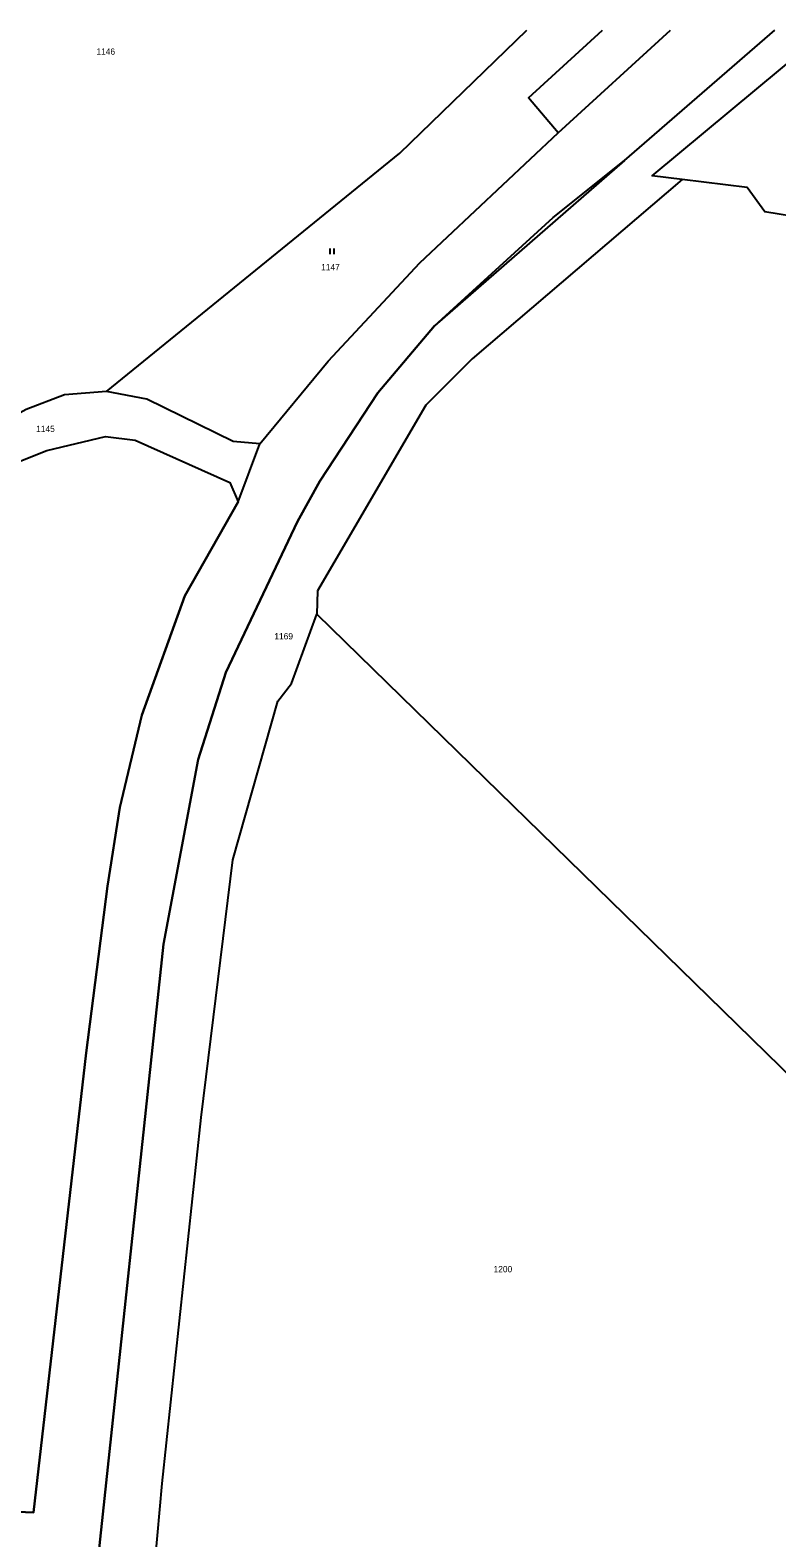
# Model space of a CAD drawing. Extents: x -520431 to -517205, y -1075927 to -1074013.
# Drawn here: x -517614 to -517411.8, y -1074423.3 to -1074014.8 of the extents above; entities that cross this region are included whole.
import ezdxf

# ---------------------------------------------------------------- set-up
doc = ezdxf.new("R2010")
doc.units = 0
for name, color, linetype in [('Hranice parcel', 7, 'Continuous'), ('Parcelní čísla', 7, 'Continuous'), ('Vrstva 54', 7, 'Continuous'), ('Značky kultur', 7, 'Continuous')]:
    doc.layers.add(name, color=color, linetype=linetype)

msp = doc.modelspace()

# ---------------------------------------------------------------- linework, layer by layer
at = {"layer": 'Hranice parcel'}
msp.add_line((-517557.7, -1074142.56), (-517551.84, -1074126.89), dxfattribs=at)
for points in [[(-517596.08, -1074449.57), (-517597.12, -1074446.25), (-517596.45, -1074436.33), (-517577.92, -1074262.43), (-517568.47, -1074212.35), (-517561.03, -1074188.8), (-517541.56, -1074147.89), (-517535.52, -1074136.96), (-517519.8, -1074113.04), (-517504.53, -1074094.89), (-517472.33, -1074065.57), (-517453.06, -1074050.06), (-517412.3, -1074014.78)], [(-517593.38, -1074112.65), (-517513.88, -1074048.1), (-517479.44, -1074014.78)], [(-517470.95, -1074042.58), (-517478.99, -1074033.08), (-517458.99, -1074014.78)], [(-517470.95, -1074042.58), (-517440.58, -1074014.78)], [(-517437.36, -1074055.27), (-517445.5, -1074054.27), (-517403.27, -1074019.12), (-517403.28, -1074024.27)], [(-517551.84, -1074126.89), (-517533.32, -1074104.45), (-517508.43, -1074077.79), (-517470.95, -1074042.58)], [(-517437.36, -1074055.27), (-517494.25, -1074103.83), (-517506.83, -1074116.4), (-517536.22, -1074166.69), (-517536.38, -1074173.02)], [(-517259.37, -1074277.35), (-517343.54, -1074154.39), (-517403.87, -1074065.85), (-517415.04, -1074064.04), (-517419.79, -1074057.44), (-517437.36, -1074055.27)], [(-517593.38, -1074112.65), (-517604.68, -1074113.55), (-517615.08, -1074117.52), (-517630.73, -1074126.27)], [(-517551.84, -1074126.89), (-517559.07, -1074126.19), (-517582.45, -1074114.78), (-517593.38, -1074112.65)], [(-517665.62, -1074146.15), (-517650.31, -1074144.88), (-517609.46, -1074128.64), (-517593.64, -1074124.88), (-517585.53, -1074125.86), (-517559.89, -1074137.38), (-517557.7, -1074142.56)], [(-517557.7, -1074142.56), (-517572.14, -1074168.03), (-517583.79, -1074200.35), (-517589.69, -1074225.41), (-517593.05, -1074246.68), (-517598.85, -1074291.89), (-517613.15, -1074416.35), (-517624.1, -1074415.98)], [(-517563.85, -1074479.09), (-517577.93, -1074457.32), (-517581.45, -1074443.71), (-517578.27, -1074408.5), (-517567.69, -1074309.38), (-517559.16, -1074239.57), (-517546.96, -1074196.61), (-517543.18, -1074191.82), (-517536.38, -1074173.02)], [(-517536.38, -1074173.02), (-517426.5, -1074280.32), (-517316.62, -1074387.64)]]:
    msp.add_lwpolyline(points, dxfattribs=at)
at = {"layer": 'Vrstva 54'}
for points in [[(-517624.1, -1074415.98), (-517613.15, -1074416.35), (-517598.85, -1074291.89), (-517593.05, -1074246.68), (-517589.69, -1074225.41), (-517583.79, -1074200.35), (-517572.14, -1074168.03), (-517557.7, -1074142.56), (-517551.84, -1074126.89), (-517533.32, -1074104.45), (-517508.43, -1074077.79), (-517470.95, -1074042.58)], [(-517453.06, -1074050.06), (-517504.53, -1074094.89), (-517519.8, -1074113.04), (-517535.52, -1074136.96), (-517541.56, -1074147.89), (-517561.03, -1074188.8), (-517568.47, -1074212.35), (-517577.92, -1074262.43), (-517596.45, -1074436.33), (-517597.12, -1074446.25), (-517596.08, -1074449.57), (-517596.68, -1074482.99), (-517602.98, -1074510.54), (-517604.71, -1074518.08), (-517594.31, -1074529.16), (-517598.94, -1074560.06), (-517610.15, -1074561.61), (-517627.46, -1074556.34)]]:
    msp.add_lwpolyline(points, dxfattribs=at)
at = {"layer": 'Značky kultur'}
for p, q in [((-517532.71, -1074075.48), (-517532.71, -1074073.98)), ((-517531.71, -1074075.48), (-517531.71, -1074073.98))]:
    msp.add_line(p, q, dxfattribs=at)

# ---------------------------------------------------------------- texts
at = {"layer": 'Parcelní čísla'}
for s, p in [('1146', (-517596.07, -1074021.44)), ('1147', (-517535.2, -1074079.85)), ('1145', (-517612.39, -1074123.66)), ('1169', (-517547.87, -1074179.84)), ('1200', (-517488.49, -1074351.3))]:
    msp.add_text(s, height=1.7, dxfattribs=at).set_placement(p)

doc.saveas('drawing.dxf')
